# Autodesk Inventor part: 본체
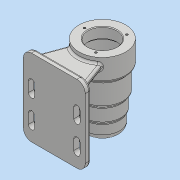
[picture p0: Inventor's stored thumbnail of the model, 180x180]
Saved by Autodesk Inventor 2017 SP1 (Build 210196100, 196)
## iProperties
Part Number: 본체
Material: 일반
Document SubType Name: Modeling
Designer: MRC
Density: 1 g/cm^3
Appearance: 기본값
Author: MRC
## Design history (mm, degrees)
sketch "스케치1"
  geometry: C1 r 34 at (0, 0); 1 further point
  constraints: 1 centre point, 1 coincident
  dimensions: "d0" = 68 diameter of C1
extrude "돌출1" new body sketch "스케치1" distance "d1" = 32; taper "d2" = 0 deg
sketch "스케치2"
  geometry: C1 r 34 at (0, 0) reference; C2 r 30 at (0, 0)
  constraints: 1 centre point, 1 coincident
  dimensions: "d3" = 60 diameter of C2
extrude "돌출2" join sketch "스케치2" distance "d4" = 34; taper "d5" = 0 deg
sketch "스케치3"
  geometry: C1 r 30 at (0, 0) reference; C2 r 27 at (0, 0)
  constraints: 1 centre point, 1 coincident
  dimensions: "d6" = 54 diameter of C2
extrude "돌출3" join sketch "스케치3" distance "d7" = 22; taper "d8" = 0 deg
sketch "스케치4"
  geometry: C1 r 27 at (0, 0) reference; C2 r 25 at (0, 0)
  constraints: 1 centre point, 1 coincident
  dimensions: "d110" = 50 diameter of C2
extrude "돌출4" join sketch "스케치4" distance "d9" = 24; taper "d10" = 0 deg
sketch "스케치5"
  geometry: C1 r 34 at (0, 0) reference; C2 r 21 at (0, 0)
  constraints: 1 centre point, 1 coincident
  dimensions: "d11" = 42 diameter of C2
extrude "돌출5" cut sketch "스케치5" distance "d12" = 15; taper "d13" = 0 deg
sketch "스케치6"
  geometry: C1 r 21 at (0, 0) reference; C2 r 24 at (0, 0)
  constraints: 1 centre point, 1 coincident
  dimensions: "d14" = 48 diameter of C2
extrude "돌출6" cut sketch "스케치6" distance "d15" = 54; taper "d16" = 0 deg
sketch "스케치7"
  geometry: C1 r 24 at (0, 0) reference; C2 r 21 at (0, 0)
  constraints: 1 centre point, 1 coincident
  dimensions: "d17" = 42 diameter of C2
extrude "돌출7" cut sketch "스케치7" distance "d18" = 12; taper "d19" = 0 deg
sketch "스케치8"
  geometry: C1 r 21 at (0, 0) reference; C2 r 17.5 at (0, 0)
  constraints: 1 centre point, 1 coincident
  dimensions: "d20" = 35 diameter of C2
extrude "돌출8" cut sketch "스케치8" distance "d21" = 18; taper "d22" = 0 deg
sketch "스케치9"
  geometry: C1 r 17.5 at (0, 0) reference; C2 r 16 at (0, 0)
  constraints: 1 centre point, 1 coincident
  dimensions: "d23" = 32 diameter of C2
extrude "돌출9" cut sketch "스케치9" distance "d24" = 4; taper "d25" = 0 deg
sketch "스케치10"
  geometry: C1 r 16 at (0, 0) reference; C2 r 10.5 at (0, 0)
  constraints: 1 centre point, 1 coincident
  dimensions: "d26" = 21 diameter of C2
extrude "돌출11" cut sketch "스케치10" distance "d29" = 3; taper "d30" = 0 deg
fillet "모깎기1" dims "d31" = 0.3
fillet "모깎기2" dims "d32" = 3
fillet "모깎기3" dims "d33" = 0.3
fillet "모깎기4" dims "d34" = 3
chamfer "모따기1" distance "d35" = 1; stored, may be unused: second distance "d36" = 2, angle "d37" = 45 deg
fillet "모깎기10" dims "d111" = 3
node "작업 평면1"
sketch "스케치11"
  geometry: L1 (-45, -112)-(45, -112); L2 (45, -112)-(45, 0); L3 (45, 0)-(-45, 0); L4 (-45, 0)-(-45, -112); 2 further points
  constraints: 8 end point, 2 parallel, 1 coincident, 1 horizontal, 1 midpoint, 1 perpendicular
  dimensions: "d39" = 90 distance of L3.end L2.end; "d40" = 112 distance of L2.end L1.end
extrude "돌출12" join sketch "스케치11" distance "d41" = 8; taper "d42" = 0 deg
node "작업 평면2"
sketch "스케치17"
  geometry: L1 (45, 112)-(-45, 112) reference; L2 (-45, 0)-(45, 0) reference; L3 (4, 85)-(-4, 85); L4 (-4, 85)-(-4, 8); L5 (-4, 8)-(4, 8); L6 (4, 8)-(4, 85); 3 further points
  constraints: 8 end point, 2 midpoint, 2 parallel, 1 horizontal, 1 perpendicular, 1 vertical alignment
  dimensions: "d55" = 8 distance of L3.start L3.end; "d56" = 77 distance of L5.end L3.start; "d57" = 8 distance between parallel lines of L2 L5
extrude "돌출13" join sketch "스케치17" stored distance "d58" = 8; taper "d59" = 0 deg
sketch "스케치18"
  geometry: L1 (-41, -8)-(-41, 0) reference; L2 (-41, 0)-(0, 0) reference; L3 (0, 0)-(0, 28.236) reference; L4 (8, 28.236)-(8, 0) reference; L5 (8, 0)-(49, 0) reference; L6 (49, 0)-(49, -8) reference; L7 (49, -8)-(-41, -8) reference; L8 (0, 0)-(8, 0) reference; L9 (-19.409, 37.342)-(-33, 0); C1 r 21 at (4, 62) reference; A1 r 34 centre (4, 62) between (0, 28.236) and (8, 28.236) reference; A2 r 34 centre (4, 62) between (8, 28.236) and (0, 28.236) reference
  constraints: 2 end point, 1 point on circle, 1 point on line
  dimensions: "d60" = 20 deg angle of L1 L9; "d61" = 8 distance from line of L1 L9.end
extrude "돌출14" join sketch "스케치18" distance "d62" = 8; taper "d63" = 0 deg
feature "면 기울기1" dims angle "d64" = 15 deg
fillet "모깎기5" dims "d65" = 3
fillet "모깎기6" dims "d66" = 12
sketch "스케치19"
  geometry: L1 (33, 112)-(-33, 112) reference; L2 (33, 92)-(33, 77); L3 (28.5, 92)-(28.5, 77); L4 (37.5, 77)-(37.5, 92); L5 (33, 52)-(33, 37); L6 (28.5, 52)-(28.5, 37); L7 (37.5, 37)-(37.5, 52); L8 (33, 0)-(-33, 0) reference; L9 (-45, 12)-(-45, 100) reference; L10 (-33, 112)-(33, 112) reference; L11 (45, 100)-(45, 12) reference; L12 (4, 81.894)-(4, 19) reference; L13 (7, 16)-(33.807, 16) reference; L14 (37, 13)-(37, 11) reference; L15 (33.807, 8)-(-33.807, 8) reference; L16 (-37, 11)-(-37, 13) reference; L17 (-33.807, 16)-(-7, 16) reference; L18 (-4, 19)-(-4, 81.894) reference; L19 (-1, 85)-(1, 85) reference; L20 (-33, 92)-(-33, 77); L21 (-37.5, 92)-(-37.5, 77); L22 (-28.5, 77)-(-28.5, 92); L23 (-33, 52)-(-33, 37); L24 (-37.5, 52)-(-37.5, 37); L25 (-28.5, 37)-(-28.5, 52); A1 r 4.5 centre (33, 92) between (37.5, 92) and (28.5, 92); A2 r 4.5 centre (33, 77) between (28.5, 77) and (37.5, 77); A3 r 4.5 centre (33, 52) between (37.5, 52) and (28.5, 52); A4 r 4.5 centre (33, 37) between (28.5, 37) and (37.5, 37); A5 r 12 centre (33, 12) between (33, 0) and (45, 12) reference; A6 r 12 centre (-33, 12) between (-45, 12) and (-33, 0) reference; A7 r 12 centre (-33, 100) between (-33, 112) and (-45, 100) reference; A8 r 12 centre (33, 100) between (45, 100) and (33, 112) reference; A9 r 3 centre (7, 19) between (4, 19) and (7, 16) reference; A10 r 3 centre (-7, 19) between (-7, 16) and (-4, 19) reference; A11 r 4.5 centre (-33, 92) between (-28.5, 92) and (-37.5, 92); A12 r 4.5 centre (-33, 77) between (-37.5, 77) and (-28.5, 77); A13 r 4.5 centre (-33, 52) between (-28.5, 52) and (-37.5, 52); A14 r 4.5 centre (-33, 37) between (-37.5, 37) and (-28.5, 37); 11 further points; 6 other entities
  constraints: 32 end point, 16 point on circle, 16 tangent, 8 centre point, 5 parallel, 4 midpoint, 3 vertical, 6 other
  dimensions: "d67" = 15 distance of L2.start L2.end; "d68" = 9 diameter of A2; "d69" = 15 distance of L5.start L5.end; "d70" = 9 diameter of A4; "d71" = 25 distance of L5.start L2.end; "d73" = 33 horizontal distance of point (0, 0) point (33, 84.5); "d74" = 15 distance of L20.start L20.end; "d75" = 9 diameter of A12; "d76" = 15 distance of L23.start L23.end; "d77" = 9 diameter of A14; "d78" = 33 horizontal distance of point (0, 0) point (33, 44.5); "d79" = 33 horizontal distance of point (0, 0) point (-33, 44.5); "d80" = 33 horizontal distance of point (0, 0) point (-33, 84.5); "d82" = 25 distance of L23.start L20.end; "d85" = 20 distance from line of L20.start L1; "d86" = 20 distance from line of L1 L2.start
extrude "돌출15" cut sketch "스케치19" distance "d87" = 8; taper "d88" = 0 deg
fillet "모깎기7" dims "d89" = 3
fillet "모깎기8" dims "d90" = 8
sketch "스케치20"
  geometry: L1 (33, 112)-(-33, 112) reference; A1 r 4.5 centre (33, 92) between (37.5, 92) and (28.5, 92) reference; 2 further points
  constraints: 1 other
  dimensions: "d92" = 33 horizontal distance of A1.centre point (0, 100); "d93" = 12 distance from line of L1 point (0, 100)
feature "엠보싱1" sketch "스케치20" dims "d0" = 68, "d94" = 0.5, "d95" = 0
sketch "스케치21" dims "d98" = 52
  geometry: C1 r 34 at (0, 0) reference; C2 r 22 at (0, 0) reference; 4 further points
  constraints: 1 coincident, 1 horizontal alignment, 6 other
  dimensions: "d101" = 360 deg dimension on C1.centre point (-26, 0) (derived)
hole "구멍1" sketch "스케치21" at (13, 22.517), (13, -22.517), (-26, 0) diameter "d103" = 3.242; stored, may be unused: countersink angle "d107" = 90 deg, drill point angle "d109" = 118 deg; dims "d104" = 8, "d105" = 4, "d106" = 2, "d108" = 11
fillet "모깎기11" dims "d112" = 3
node "솔리드1"
mirror "미러1"
node "절단 모서리 투영1"
node "절단 모서리 투영2"
other parameters: "d46" = -12
